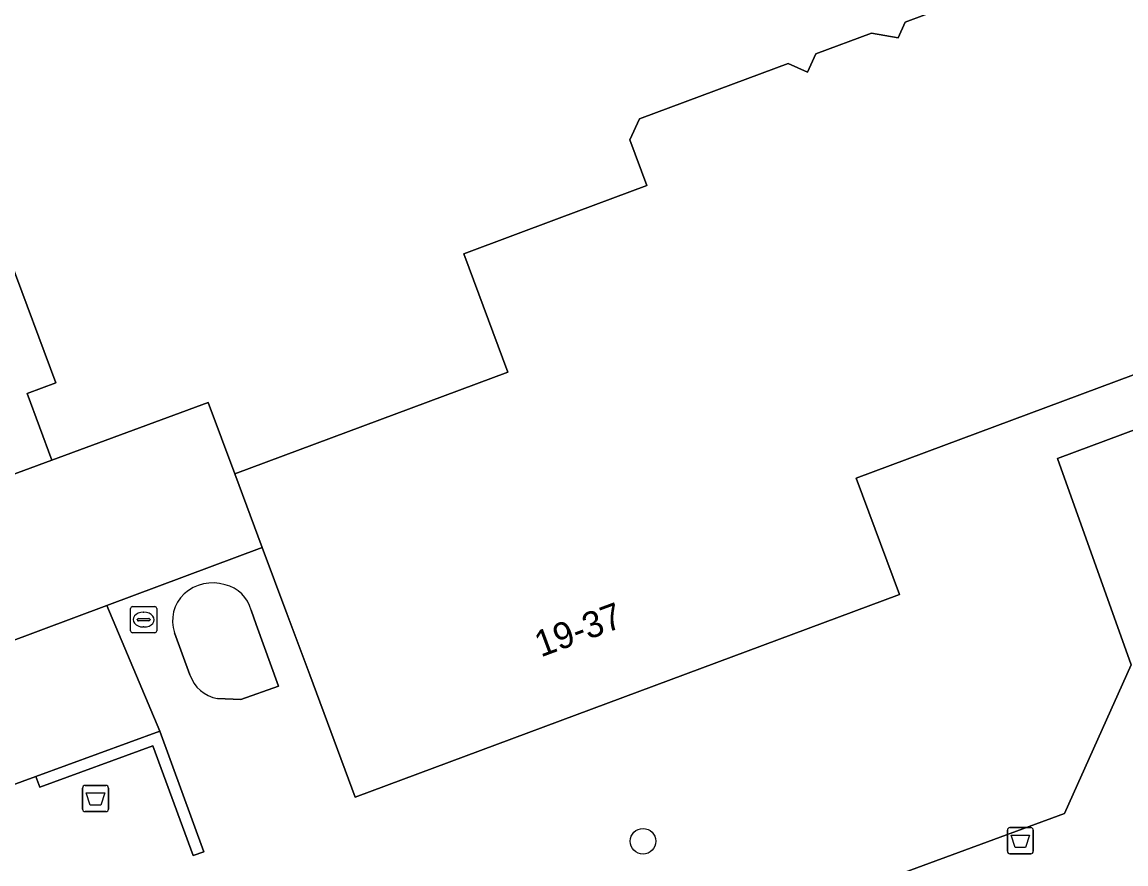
# Model space of a CAD drawing. Extents: x 160806 to 161707, y 383696 to 384148.
# Drawn here: x 161057.39 to 161099.49, y 383897.89 to 383930.02 of the extents above; entities that cross this region are included whole.
import ezdxf

# ---------------------------------------------------------------- set-up
doc = ezdxf.new("R2010")
doc.units = 0
for name, color, linetype in [('IMGEO_Afvalbak', 7, 'Continuous'), ('IMGEO_Boom', 7, 'Continuous'), ('IMGEO_Muur', 7, 'Continuous'), ('IMGEO_Pand', 7, 'Continuous'), ('IMGEO_Pand_nummerreeks', 7, 'Continuous'), ('IMGEO_Rijbaan_lokaal_gesloten', 7, 'Continuous'), ('IMGEO_Rioolput', 7, 'Continuous'), ('IMGEO_Terreindeel_gesloten', 7, 'Continuous'), ('IMGEO_Voetpad_open', 7, 'Continuous')]:
    doc.layers.add(name, color=color, linetype=linetype)

msp = doc.modelspace()

# ---------------------------------------------------------------- linework, layer by layer
at = {"layer": 'IMGEO_Afvalbak'}
for p, q in [((161059.799, 383900.888), (161060.589, 383900.888)), ((161060.589, 383900.888), (161059.799, 383900.888)), ((161059.699, 383899.988), (161059.699, 383900.788)), ((161059.699, 383900.788), (161059.699, 383899.988)), ((161060.689, 383900.788), (161060.689, 383899.988)), ((161060.689, 383899.988), (161060.689, 383900.788)), ((161060.589, 383899.888), (161059.799, 383899.888)), ((161059.799, 383899.888), (161060.589, 383899.888)), ((161095.072, 383899.277), (161095.862, 383899.277)), ((161095.862, 383899.277), (161095.072, 383899.277)), ((161094.972, 383898.377), (161094.972, 383899.177)), ((161094.972, 383899.177), (161094.972, 383898.377)), ((161095.962, 383899.177), (161095.962, 383898.377)), ((161095.962, 383898.377), (161095.962, 383899.177)), ((161095.862, 383898.277), (161095.072, 383898.277)), ((161095.072, 383898.277), (161095.862, 383898.277))]:
    msp.add_line(p, q, dxfattribs=at)
for points in [[(161059.842, 383900.602), (161060.546, 383900.602), (161060.397, 383900.132), (161059.991, 383900.132), (161059.842, 383900.602)], [(161095.115, 383898.991), (161095.819, 383898.991), (161095.67, 383898.521), (161095.264, 383898.521), (161095.115, 383898.991)]]:
    msp.add_lwpolyline(points, dxfattribs=at)
for centre, start, end in [((161059.799, 383900.788), 90, 180), ((161059.799, 383900.788), 90, 180), ((161060.589, 383900.788), 0, 90), ((161060.589, 383900.788), 360, 90), ((161059.799, 383899.988), 180, 270), ((161059.799, 383899.988), 180, 270), ((161060.589, 383899.988), 270, 0), ((161060.589, 383899.988), 270, 0), ((161095.072, 383899.177), 90, 180), ((161095.072, 383899.177), 90, 180), ((161095.862, 383899.177), 0, 90), ((161095.862, 383899.177), 360, 90), ((161095.072, 383898.377), 180, 270), ((161095.072, 383898.377), 180, 270), ((161095.862, 383898.377), 270, 0), ((161095.862, 383898.377), 270, 0)]:
    msp.add_arc(centre, 0.1, start, end, dxfattribs=at)
at = {"layer": 'IMGEO_Boom'}
msp.add_circle((161081.077, 383898.759), 0.489, dxfattribs=at)
at = {"layer": 'IMGEO_Muur'}
msp.add_lwpolyline([(161057.923, 383901.231), (161058.075, 383900.818), (161062.384, 383902.397), (161063.919, 383898.209), (161064.332, 383898.36), (161062.646, 383902.961)], close=True, dxfattribs=at)
at = {"layer": 'IMGEO_Pand'}
for points in [[(161093.331, 383930.85), (161091.076, 383930.01), (161090.806, 383929.418), (161089.793, 383929.589), (161087.67, 383928.798), (161087.35, 383928.099), (161086.612, 383928.436), (161085.627, 383928.069), (161080.941, 383926.324), (161080.576, 383925.525), (161081.227, 383923.776), (161077.873, 383922.527), (161074.242, 383921.174), (161075.925, 383916.657), (161065.506, 383912.776), (161066.551, 383909.97), (161067.49, 383907.448), (161068.363, 383905.105), (161070.1, 383900.443), (161083.887, 383905.58), (161090.861, 383908.178), (161089.207, 383912.618), (161106.369, 383919.012)], [(161053.421, 383911.413), (161058.534, 383913.302), (161057.594, 383915.845), (161058.676, 383916.245), (161056.943, 383920.935)], [(161064.847, 383904.207), (161065.737, 383904.17), (161067.169, 383904.68), (161066.324, 383907.033), (161066.13, 383907.574)], [(161063.213, 383906.713), (161063.795, 383905.112)]]:
    msp.add_lwpolyline(points, dxfattribs=at)
for centre, radius, start, end in [((161064.653, 383907.004), 1.61, 72.5301, 132.1393), ((161064.857, 383907.258), 1.312, 13.9277, 77.7092), ((161064.521, 383907.183), 1.389, 133.0557, 199.7632), ((161065.064, 383905.523), 1.334, 197.9557, 260.6357)]:
    msp.add_arc(centre, radius, start, end, dxfattribs=at)
at = {"layer": 'IMGEO_Rijbaan_lokaal_gesloten'}
for points in [[(161060.631, 383907.756), (161066.551, 383909.97), (161065.506, 383912.776), (161064.49, 383915.503), (161058.534, 383913.302), (161053.421, 383911.413), (161053.4, 383911.47), (161049.695, 383910.101), (161043.72, 383907.911), (161043.624, 383908.173), (161042.42, 383907.727), (161033.437, 383904.394), (161034.783, 383900.781), (161036.286, 383901.335), (161039.086, 383901.965), (161041.846, 383901.934), (161043.103, 383901.391), (161044.432, 383899.991), (161044.961, 383898.608), (161045.706, 383896.613), (161049.823, 383898.173)], [(161053.746, 383905.182), (161055.478, 383905.83), (161060.631, 383907.756)]]:
    msp.add_lwpolyline(points, dxfattribs=at)
at = {"layer": 'IMGEO_Rioolput'}
for p, q in [((161061.531, 383906.788), (161061.531, 383907.64)), ((161061.606, 383907.714), (161062.458, 383907.714)), ((161062.532, 383907.64), (161062.532, 383906.788)), ((161061.79, 383907.208), (161061.79, 383907.22)), ((161061.833, 383907.257), (161062.231, 383907.257)), ((161062.019, 383907.494), (161062.044, 383907.494)), ((161062.274, 383907.22), (161062.274, 383907.208)), ((161062.228, 383907.171), (161061.83, 383907.171)), ((161062.042, 383906.934), (161062.017, 383906.934)), ((161062.458, 383906.714), (161061.606, 383906.714))]:
    msp.add_line(p, q, dxfattribs=at)
for points in [[(161061.531, 383906.788), (161061.531, 383907.64)], [(161061.606, 383907.714), (161062.458, 383907.714)], [(161062.532, 383907.64), (161062.532, 383906.788)], [(161062.458, 383906.714), (161061.606, 383906.714)]]:
    msp.add_lwpolyline(points, dxfattribs=at)
for centre, radius, start, end in [((161061.608, 383907.638), 0.0765, 91.552, 178.448), ((161061.608, 383907.638), 0.0765, 91.552, 178.448), ((161062.456, 383907.638), 0.0765, 1.552, 88.448), ((161062.456, 383907.638), 0.0765, 1.552, 88.448), ((161061.83, 383907.217), 0.0403, 85.8775, 175.7526), ((161061.827, 383907.207), 0.0366, 178.938, 274.7102), ((161062.231, 383907.214), 0.043, 264.8664, 352.4533), ((161062.235, 383907.219), 0.0386, 1.7309, 96.639), ((161061.608, 383906.79), 0.0765, 181.552, 268.448), ((161061.608, 383906.79), 0.0765, 181.552, 268.448), ((161062.456, 383906.79), 0.0765, 271.552, 358.448), ((161062.456, 383906.79), 0.0765, 271.552, 358.448)]:
    msp.add_arc(centre, radius, start, end, dxfattribs=at)
for centre, major_axis, ratio, start_param, end_param in [((161062.018, 383907.214), (-0.387, 0.002), 0.722429, 4.712389, 7.853982), ((161062.043, 383907.214), (-0.39, 0.002), 0.717154, 1.570796, 4.712389)]:
    msp.add_ellipse(centre, major_axis=major_axis, ratio=ratio, start_param=start_param, end_param=end_param, dxfattribs=at)
at = {"layer": 'IMGEO_Terreindeel_gesloten'}
for points in [[(161056.247, 383885.258), (161085.633, 383896.162), (161086.368, 383895.852), (161097.15, 383899.812), (161099.69, 383905.487), (161096.881, 383913.365), (161111.083, 383918.654), (161110.447, 383920.534), (161114.626, 383922.225), (161106.884, 383947.107)], [(161101.771, 383931.352), (161103.75, 383926.041), (161104.623, 383923.698), (161106.369, 383919.012), (161089.207, 383912.618), (161090.861, 383908.178), (161083.887, 383905.58), (161070.1, 383900.443), (161068.363, 383905.105), (161067.49, 383907.448), (161066.551, 383909.97), (161060.631, 383907.756), (161062.646, 383902.961), (161064.332, 383898.36), (161063.919, 383898.209), (161062.384, 383902.397), (161058.075, 383900.818), (161057.923, 383901.231), (161055.575, 383900.371)], [(161056.943, 383920.935), (161058.676, 383916.245), (161057.594, 383915.845), (161058.534, 383913.302), (161064.49, 383915.503), (161065.506, 383912.776), (161075.925, 383916.657), (161074.242, 383921.174), (161077.873, 383922.527), (161081.227, 383923.776), (161080.576, 383925.525), (161080.941, 383926.324), (161085.627, 383928.069), (161086.612, 383928.436), (161087.35, 383928.099), (161087.67, 383928.798), (161089.793, 383929.589), (161090.806, 383929.418), (161091.076, 383930.01), (161093.331, 383930.85)], [(161066.13, 383907.574), (161066.324, 383907.033), (161067.169, 383904.68), (161065.737, 383904.17), (161064.847, 383904.207)], [(161063.795, 383905.112), (161063.213, 383906.713)]]:
    msp.add_lwpolyline(points, dxfattribs=at)
for centre, radius, start, end in [((161064.653, 383907.004), 1.61, 72.5301, 132.1393), ((161064.857, 383907.258), 1.312, 13.9277, 77.7092), ((161064.521, 383907.183), 1.389, 133.0557, 199.7632), ((161065.064, 383905.523), 1.334, 197.9557, 260.6357)]:
    msp.add_arc(centre, radius, start, end, dxfattribs=at)
at = {"layer": 'IMGEO_Voetpad_open'}
for points in [[(161104.271, 383910.409), (161105.892, 383913.881), (161118.631, 383914.703), (161118.837, 383915.091), (161117.416, 383919.839), (161117.213, 383920.012), (161114.626, 383922.225), (161110.447, 383920.534), (161111.083, 383918.654), (161096.881, 383913.365), (161099.69, 383905.487), (161097.15, 383899.812), (161086.368, 383895.852), (161085.633, 383896.162), (161056.247, 383885.258), (161056.426, 383884.769), (161056.013, 383884.618), (161054.963, 383884.085)], [(161050.88, 383898.651), (161055.575, 383900.371), (161057.923, 383901.231), (161062.646, 383902.961), (161060.631, 383907.756), (161055.478, 383905.83), (161053.746, 383905.182)]]:
    msp.add_lwpolyline(points, dxfattribs=at)

# ---------------------------------------------------------------- texts
at = {"layer": 'IMGEO_Pand_nummerreeks'}
msp.add_text('19-37', height=1, rotation=20.4341, dxfattribs=at).set_placement((161077.178, 383905.769))

doc.saveas('drawing.dxf')
